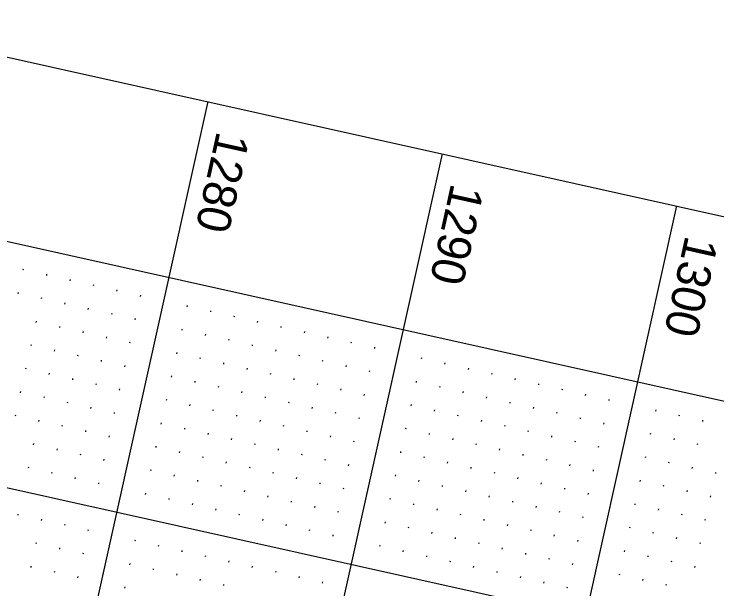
# Model space of a CAD drawing. Extents: x 2149268 to 2150830, y 142155 to 144285.
# Drawn here: x 2149824.8 to 2149971.3, y 143841.2 to 143960.9 of the extents above; entities that cross this region are included whole.
import ezdxf

# ---------------------------------------------------------------- set-up
doc = ezdxf.new("R2010")
doc.units = 0
for name, color, linetype in [('SHT_Plan_Profile_Sheet_Elev_Txt', 7, 'Continuous'), ('SHT_Profile_Grid_Major', 7, 'Continuous'), ('SHT_Profile_Grid_Minor', 7, 'Continuous'), ('SHT_Sheet_Border', 7, 'Continuous')]:
    doc.layers.add(name, color=color, linetype=linetype)

msp = doc.modelspace()

# ---------------------------------------------------------------- linework, layer by layer
at = {"layer": 'SHT_Profile_Grid_Major'}
for p, q in [((2149865.21, 143942.67), (2149523.35, 142405.21)), ((2149914.02, 143931.81), (2149572.16, 142394.36)), ((2149962.83, 143920.96), (2149620.97, 142383.51)), ((2149699.8, 143889.81), (2150187.88, 143781.28))]:
    msp.add_line(p, q, dxfattribs=at)
at = {"layer": 'SHT_Profile_Grid_Minor'}
for p, q in [((2149826.73, 143907.81), (2149826.68, 143907.57)), ((2149831.61, 143906.73), (2149831.56, 143906.48)), ((2149836.49, 143905.64), (2149836.44, 143905.4)), ((2149841.37, 143904.56), (2149841.32, 143904.31)), ((2149825.65, 143902.93), (2149825.59, 143902.69)), ((2149846.25, 143903.47), (2149846.2, 143903.23)), ((2149830.53, 143901.85), (2149830.47, 143901.6)), ((2149851.14, 143902.39), (2149851.08, 143902.14)), ((2149835.41, 143900.76), (2149835.35, 143900.52)), ((2149840.29, 143899.68), (2149840.23, 143899.43)), ((2149860.9, 143900.22), (2149860.84, 143899.97)), ((2149845.17, 143898.59), (2149845.12, 143898.35)), ((2149865.78, 143899.13), (2149865.72, 143898.89)), ((2149870.66, 143898.04), (2149870.6, 143897.8)), ((2149829.44, 143896.97), (2149829.39, 143896.72)), ((2149850.05, 143897.5), (2149850, 143897.26)), ((2149875.54, 143896.96), (2149875.49, 143896.72)), ((2149834.32, 143895.88), (2149834.27, 143895.64)), ((2149859.81, 143895.33), (2149859.76, 143895.09)), ((2149880.42, 143895.87), (2149880.37, 143895.63)), ((2149839.2, 143894.79), (2149839.15, 143894.55)), ((2149844.08, 143893.71), (2149844.03, 143893.47)), ((2149864.69, 143894.25), (2149864.64, 143894)), ((2149885.3, 143894.79), (2149885.25, 143894.54)), ((2149890.18, 143893.7), (2149890.13, 143893.46)), ((2149848.96, 143892.62), (2149848.91, 143892.38)), ((2149869.57, 143893.16), (2149869.52, 143892.92)), ((2149895.06, 143892.62), (2149895.01, 143892.37)), ((2149828.36, 143892.08), (2149828.3, 143891.84)), ((2149833.24, 143891), (2149833.18, 143890.76)), ((2149874.45, 143892.08), (2149874.4, 143891.83)), ((2149879.33, 143890.99), (2149879.28, 143890.75)), ((2149899.94, 143891.53), (2149899.89, 143891.29)), ((2149838.12, 143889.91), (2149838.06, 143889.67)), ((2149858.73, 143890.45), (2149858.67, 143890.21)), ((2149863.61, 143889.37), (2149863.55, 143889.12)), ((2149884.22, 143889.91), (2149884.16, 143889.66)), ((2149909.71, 143889.36), (2149909.65, 143889.12)), ((2149843, 143888.83), (2149842.94, 143888.58)), ((2149868.49, 143888.28), (2149868.43, 143888.04)), ((2149889.1, 143888.82), (2149889.04, 143888.58)), ((2149914.59, 143888.28), (2149914.53, 143888.03)), ((2149827.27, 143887.2), (2149827.22, 143886.96)), ((2149847.88, 143887.74), (2149847.83, 143887.5)), ((2149873.37, 143887.2), (2149873.31, 143886.95)), ((2149893.98, 143887.74), (2149893.92, 143887.49)), ((2149898.86, 143886.65), (2149898.8, 143886.41)), ((2149919.47, 143887.19), (2149919.41, 143886.95)), ((2149832.15, 143886.12), (2149832.1, 143885.87)), ((2149837.03, 143885.03), (2149836.98, 143884.79)), ((2149857.64, 143885.57), (2149857.59, 143885.33)), ((2149878.25, 143886.11), (2149878.2, 143885.87)), ((2149883.13, 143885.03), (2149883.08, 143884.78)), ((2149924.35, 143886.11), (2149924.29, 143885.86)), ((2149929.23, 143885.02), (2149929.17, 143884.78)), ((2149841.91, 143883.95), (2149841.86, 143883.7)), ((2149862.52, 143884.49), (2149862.47, 143884.24)), ((2149867.4, 143883.4), (2149867.35, 143883.16)), ((2149888.01, 143883.94), (2149887.96, 143883.7)), ((2149908.62, 143884.48), (2149908.57, 143884.24)), ((2149913.5, 143883.4), (2149913.45, 143883.15)), ((2149934.11, 143883.94), (2149934.05, 143883.69)), ((2149826.19, 143882.32), (2149826.13, 143882.08)), ((2149846.79, 143882.86), (2149846.74, 143882.62)), ((2149872.28, 143882.32), (2149872.23, 143882.07)), ((2149892.89, 143882.86), (2149892.84, 143882.61)), ((2149918.38, 143882.31), (2149918.33, 143882.07)), ((2149938.99, 143882.85), (2149938.94, 143882.61)), ((2149831.07, 143881.24), (2149831.01, 143880.99)), ((2149856.56, 143880.69), (2149856.5, 143880.45)), ((2149877.16, 143881.23), (2149877.11, 143880.99)), ((2149897.77, 143881.77), (2149897.72, 143881.53)), ((2149923.26, 143881.23), (2149923.21, 143880.98)), ((2149943.87, 143881.77), (2149943.82, 143881.52)), ((2149948.75, 143880.68), (2149948.7, 143880.44)), ((2149835.95, 143880.15), (2149835.89, 143879.91)), ((2149840.83, 143879.07), (2149840.77, 143878.82)), ((2149861.44, 143879.61), (2149861.38, 143879.36)), ((2149882.05, 143880.15), (2149881.99, 143879.9)), ((2149886.93, 143879.06), (2149886.87, 143878.82)), ((2149907.53, 143879.6), (2149907.48, 143879.36)), ((2149928.14, 143880.14), (2149928.09, 143879.9)), ((2149933.02, 143879.06), (2149932.97, 143878.81)), ((2149845.71, 143877.98), (2149845.65, 143877.74)), ((2149866.32, 143878.52), (2149866.26, 143878.28)), ((2149891.81, 143877.98), (2149891.75, 143877.73)), ((2149912.42, 143878.52), (2149912.36, 143878.27)), ((2149937.9, 143877.97), (2149937.85, 143877.73)), ((2149958.51, 143878.51), (2149958.46, 143878.27)), ((2149825.1, 143877.44), (2149825.05, 143877.2)), ((2149829.98, 143876.36), (2149829.93, 143876.11)), ((2149871.2, 143877.44), (2149871.14, 143877.19)), ((2149876.08, 143876.35), (2149876.02, 143876.11)), ((2149896.69, 143876.89), (2149896.63, 143876.65)), ((2149917.3, 143877.43), (2149917.24, 143877.19)), ((2149922.18, 143876.34), (2149922.12, 143876.1)), ((2149942.79, 143876.88), (2149942.73, 143876.64)), ((2149963.39, 143877.42), (2149963.34, 143877.18)), ((2149968.27, 143876.34), (2149968.22, 143876.09)), ((2149834.86, 143875.27), (2149834.81, 143875.03)), ((2149855.47, 143875.81), (2149855.42, 143875.57)), ((2149860.35, 143874.73), (2149860.3, 143874.48)), ((2149880.96, 143875.27), (2149880.91, 143875.02)), ((2149906.45, 143874.72), (2149906.39, 143874.48)), ((2149927.06, 143875.26), (2149927, 143875.02)), ((2149947.67, 143875.8), (2149947.61, 143875.56)), ((2149839.74, 143874.19), (2149839.69, 143873.94)), ((2149865.23, 143873.64), (2149865.18, 143873.4)), ((2149885.84, 143874.18), (2149885.79, 143873.94)), ((2149911.33, 143873.63), (2149911.28, 143873.39)), ((2149931.94, 143874.17), (2149931.88, 143873.93)), ((2149957.43, 143873.63), (2149957.37, 143873.38)), ((2149844.62, 143873.1), (2149844.57, 143872.86)), ((2149870.11, 143872.56), (2149870.06, 143872.31)), ((2149890.72, 143873.09), (2149890.67, 143872.85)), ((2149895.6, 143872.01), (2149895.55, 143871.77)), ((2149916.21, 143872.55), (2149916.16, 143872.31)), ((2149936.82, 143873.09), (2149936.76, 143872.85)), ((2149941.7, 143872), (2149941.65, 143871.76)), ((2149962.31, 143872.54), (2149962.25, 143872.3)), ((2149828.9, 143871.48), (2149828.84, 143871.23)), ((2149833.78, 143870.39), (2149833.72, 143870.15)), ((2149854.39, 143870.93), (2149854.33, 143870.69)), ((2149874.99, 143871.47), (2149874.94, 143871.23)), ((2149879.87, 143870.38), (2149879.82, 143870.14)), ((2149921.09, 143871.46), (2149921.04, 143871.22)), ((2149925.97, 143870.38), (2149925.92, 143870.13)), ((2149946.58, 143870.92), (2149946.53, 143870.67)), ((2149967.19, 143871.46), (2149967.14, 143871.21)), ((2149838.66, 143869.31), (2149838.6, 143869.06)), ((2149859.27, 143869.85), (2149859.21, 143869.6)), ((2149864.15, 143868.76), (2149864.09, 143868.52)), ((2149884.76, 143869.3), (2149884.7, 143869.06)), ((2149905.36, 143869.84), (2149905.31, 143869.6)), ((2149910.24, 143868.75), (2149910.19, 143868.51)), ((2149930.85, 143869.29), (2149930.8, 143869.05)), ((2149956.34, 143868.75), (2149956.29, 143868.5)), ((2149843.54, 143868.22), (2149843.48, 143867.98)), ((2149869.03, 143867.67), (2149868.97, 143867.43)), ((2149889.64, 143868.21), (2149889.58, 143867.97)), ((2149915.13, 143867.67), (2149915.07, 143867.42)), ((2149935.73, 143868.21), (2149935.68, 143867.96)), ((2149961.22, 143867.66), (2149961.17, 143867.42)), ((2149827.81, 143866.6), (2149827.76, 143866.35)), ((2149853.3, 143866.05), (2149853.25, 143865.81)), ((2149873.91, 143866.59), (2149873.85, 143866.35)), ((2149894.52, 143867.13), (2149894.46, 143866.88)), ((2149920.01, 143866.58), (2149919.95, 143866.34)), ((2149940.61, 143867.12), (2149940.56, 143866.88)), ((2149945.5, 143866.04), (2149945.44, 143865.79)), ((2149966.1, 143866.58), (2149966.05, 143866.33)), ((2149832.69, 143865.51), (2149832.64, 143865.27)), ((2149837.57, 143864.42), (2149837.52, 143864.18)), ((2149858.18, 143864.96), (2149858.13, 143864.72)), ((2149878.79, 143865.5), (2149878.74, 143865.26)), ((2149883.67, 143864.42), (2149883.62, 143864.17)), ((2149904.28, 143864.96), (2149904.22, 143864.71)), ((2149924.89, 143865.5), (2149924.83, 143865.25)), ((2149929.77, 143864.41), (2149929.71, 143864.17)), ((2149970.98, 143865.49), (2149970.93, 143865.25)), ((2149842.45, 143863.34), (2149842.4, 143863.1)), ((2149863.06, 143863.88), (2149863.01, 143863.63)), ((2149888.55, 143863.33), (2149888.5, 143863.09)), ((2149909.16, 143863.87), (2149909.11, 143863.63)), ((2149934.65, 143863.33), (2149934.59, 143863.08)), ((2149955.26, 143863.87), (2149955.2, 143863.62)), ((2149867.94, 143862.79), (2149867.89, 143862.55)), ((2149872.82, 143861.71), (2149872.77, 143861.46)), ((2149893.43, 143862.25), (2149893.38, 143862)), ((2149914.04, 143862.79), (2149913.99, 143862.54)), ((2149918.92, 143861.7), (2149918.87, 143861.46)), ((2149939.53, 143862.24), (2149939.48, 143862)), ((2149960.14, 143862.78), (2149960.08, 143862.54)), ((2149965.02, 143861.7), (2149964.96, 143861.45)), ((2149852.21, 143861.17), (2149852.16, 143860.92)), ((2149857.1, 143860.08), (2149857.04, 143859.84)), ((2149877.7, 143860.62), (2149877.65, 143860.38)), ((2149903.19, 143860.08), (2149903.14, 143859.83)), ((2149923.8, 143860.62), (2149923.75, 143860.37)), ((2149944.41, 143861.16), (2149944.36, 143860.91)), ((2149969.9, 143860.61), (2149969.85, 143860.37)), ((2149861.98, 143859), (2149861.92, 143858.75)), ((2149882.58, 143859.54), (2149882.53, 143859.29)), ((2149908.07, 143858.99), (2149908.02, 143858.75)), ((2149928.68, 143859.53), (2149928.63, 143859.29)), ((2149954.17, 143858.99), (2149954.12, 143858.74)), ((2149866.86, 143857.91), (2149866.8, 143857.67)), ((2149887.47, 143858.45), (2149887.41, 143858.21)), ((2149892.35, 143857.37), (2149892.29, 143857.12)), ((2149912.95, 143857.91), (2149912.9, 143857.66)), ((2149933.56, 143858.45), (2149933.51, 143858.2)), ((2149938.44, 143857.36), (2149938.39, 143857.12)), ((2149959.05, 143857.9), (2149959, 143857.66)), ((2149825.64, 143856.83), (2149825.59, 143856.59)), ((2149830.52, 143855.75), (2149830.47, 143855.5)), ((2149871.74, 143856.83), (2149871.68, 143856.58)), ((2149876.62, 143855.74), (2149876.56, 143855.5)), ((2149917.84, 143856.82), (2149917.78, 143856.58)), ((2149922.72, 143855.74), (2149922.66, 143855.49)), ((2149943.32, 143856.28), (2149943.27, 143856.03)), ((2149963.93, 143856.82), (2149963.88, 143856.57)), ((2149968.81, 143855.73), (2149968.76, 143855.49)), ((2149835.4, 143854.66), (2149835.35, 143854.42)), ((2149881.5, 143854.66), (2149881.45, 143854.41)), ((2149902.11, 143855.2), (2149902.05, 143854.95)), ((2149906.99, 143854.11), (2149906.93, 143853.87)), ((2149927.6, 143854.65), (2149927.54, 143854.41)), ((2149953.09, 143854.11), (2149953.03, 143853.86)), ((2149840.28, 143853.58), (2149840.23, 143853.33)), ((2149886.38, 143853.57), (2149886.33, 143853.33)), ((2149911.87, 143853.03), (2149911.82, 143852.78)), ((2149932.48, 143853.57), (2149932.42, 143853.32)), ((2149957.97, 143853.02), (2149957.91, 143852.78)), ((2149850.04, 143851.41), (2149849.99, 143851.16)), ((2149891.26, 143852.49), (2149891.21, 143852.24)), ((2149916.75, 143851.94), (2149916.7, 143851.7)), ((2149937.36, 143852.48), (2149937.3, 143852.24)), ((2149942.24, 143851.4), (2149942.19, 143851.15)), ((2149962.85, 143851.94), (2149962.79, 143851.69)), ((2149829.44, 143850.87), (2149829.38, 143850.62)), ((2149834.32, 143849.78), (2149834.26, 143849.54)), ((2149854.93, 143850.32), (2149854.87, 143850.08)), ((2149901.02, 143850.32), (2149900.97, 143850.07)), ((2149921.63, 143850.86), (2149921.58, 143850.61)), ((2149926.51, 143849.77), (2149926.46, 143849.53)), ((2149967.73, 143850.85), (2149967.67, 143850.61)), ((2149839.2, 143848.7), (2149839.14, 143848.45)), ((2149859.81, 143849.24), (2149859.75, 143848.99)), ((2149905.9, 143849.23), (2149905.85, 143848.99)), ((2149931.39, 143848.69), (2149931.34, 143848.44)), ((2149952, 143849.22), (2149951.95, 143848.98)), ((2149864.69, 143848.15), (2149864.63, 143847.91)), ((2149869.57, 143847.07), (2149869.51, 143846.82)), ((2149910.78, 143848.15), (2149910.73, 143847.9)), ((2149915.67, 143847.06), (2149915.61, 143846.82)), ((2149936.27, 143847.6), (2149936.22, 143847.36)), ((2149956.88, 143848.14), (2149956.83, 143847.9)), ((2149961.76, 143847.05), (2149961.71, 143846.81)), ((2149828.35, 143845.99), (2149828.3, 143845.74)), ((2149848.96, 143846.53), (2149848.9, 143846.28)), ((2149853.84, 143845.44), (2149853.79, 143845.2)), ((2149874.45, 143845.98), (2149874.39, 143845.74)), ((2149920.55, 143845.97), (2149920.49, 143845.73)), ((2149941.15, 143846.51), (2149941.1, 143846.27)), ((2149966.64, 143845.97), (2149966.59, 143845.72)), ((2149833.23, 143844.9), (2149833.18, 143844.66)), ((2149858.72, 143844.36), (2149858.67, 143844.11)), ((2149879.33, 143844.9), (2149879.27, 143844.65)), ((2149925.43, 143844.89), (2149925.37, 143844.65)), ((2149950.92, 143844.34), (2149950.86, 143844.1)), ((2149838.11, 143843.82), (2149838.06, 143843.57)), ((2149863.6, 143843.27), (2149863.55, 143843.03)), ((2149884.21, 143843.81), (2149884.16, 143843.57)), ((2149889.09, 143842.72), (2149889.04, 143842.48)), ((2149930.31, 143843.8), (2149930.25, 143843.56)), ((2149935.19, 143842.72), (2149935.13, 143842.48)), ((2149955.8, 143843.26), (2149955.74, 143843.01)), ((2149847.87, 143841.65), (2149847.82, 143841.4)), ((2149868.48, 143842.19), (2149868.43, 143841.94)), ((2149940.07, 143841.63), (2149940.01, 143841.39)), ((2149960.68, 143842.17), (2149960.62, 143841.93))]:
    msp.add_line(p, q, dxfattribs=at)
at = {"layer": 'SHT_Sheet_Border'}
msp.add_line((2149710.65, 143938.62), (2150198.73, 143830.09), dxfattribs=at)
msp.add_lwpolyline([(2150726.67, 143751.11), (2150384.81, 142213.66), (2149359.84, 142441.57), (2149701.71, 143979.02)], close=True, dxfattribs=at)

# ---------------------------------------------------------------- texts
at = {"layer": 'SHT_Plan_Profile_Sheet_Elev_Txt'}
for s, p in [('1280', (2149867.12, 143936.71)), ('1290', (2149915.93, 143925.86)), ('1300', (2149964.74, 143915.01))]:
    msp.add_text(s, height=7, rotation=257.4638, dxfattribs=at).set_placement(p)

doc.saveas('drawing.dxf')
